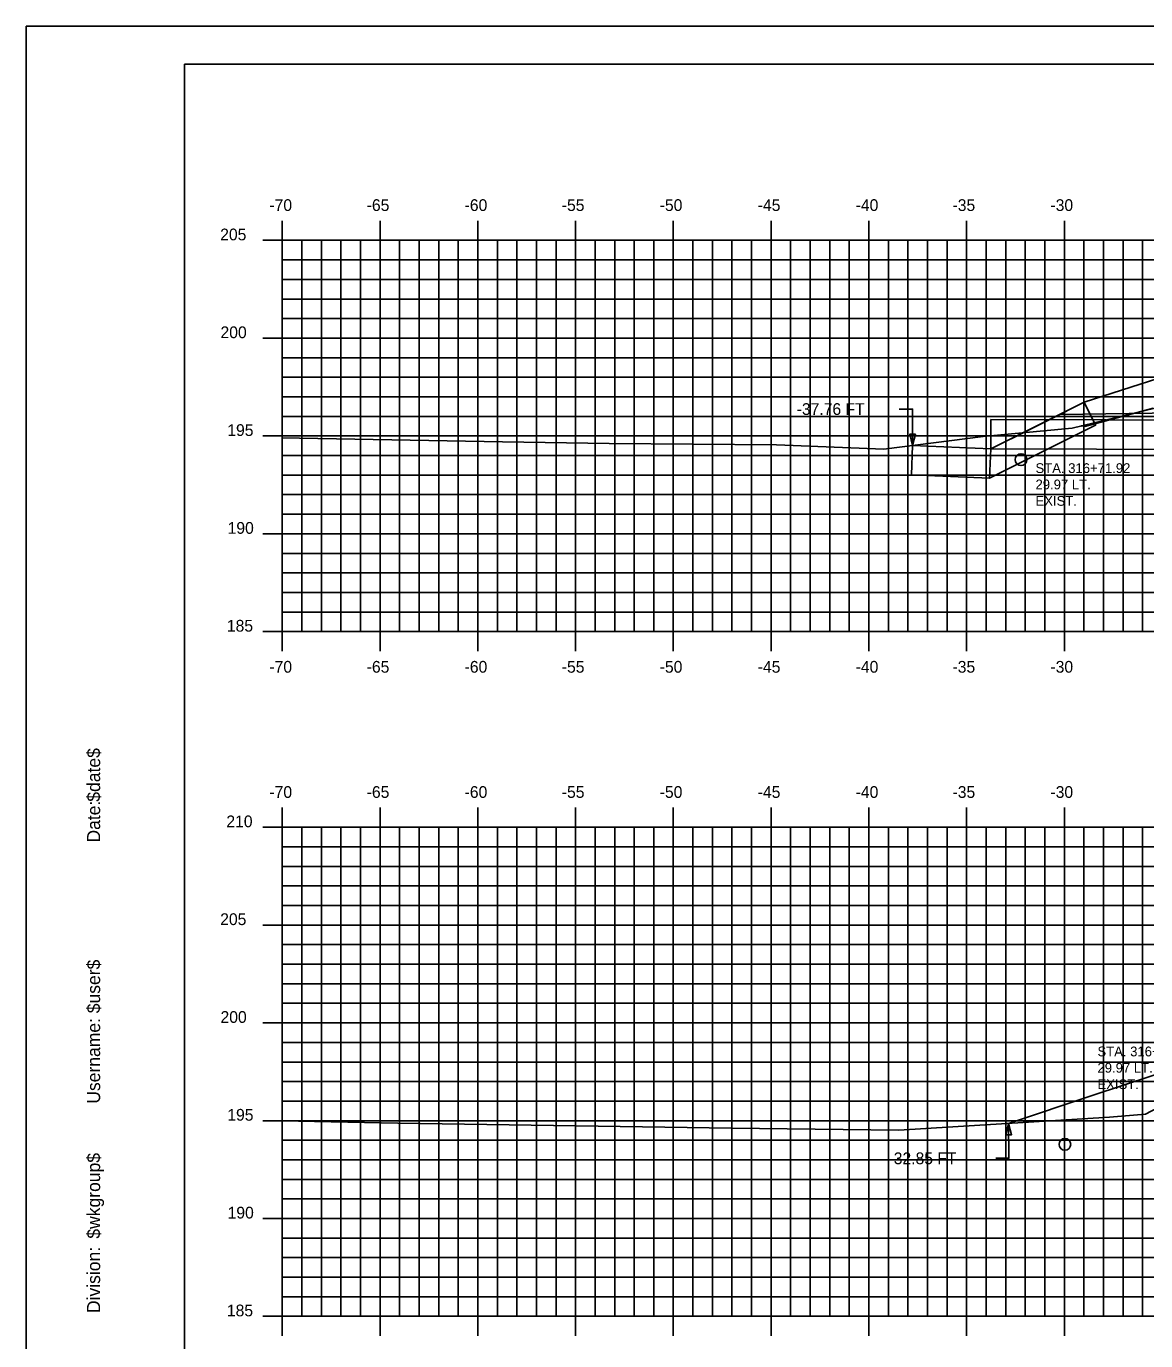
# Model space of a CAD drawing. Extents: x 1138763 to 1138933, y 608981 to 609091.
# Drawn here: x 1138763.1 to 1138820.4, y 609024.1 to 609091.3 of the extents above; entities that cross this region are included whole.
import ezdxf

# ---------------------------------------------------------------- set-up
doc = ezdxf.new("R2010")
doc.units = 0
for name, color, linetype in [('BORDER', 7, 'Continuous'), ('D_Drainage_Culvert', 7, 'Continuous'), ('D_Roadway_SlopeLines', 7, 'Continuous'), ('D_Roadway_SubGrade', 7, 'Continuous'), ('D_Text_Monospaced', 7, 'Continuous'), ('D_Text_Standard', 7, 'Continuous'), ('H_V ANNOTATION', 7, 'Continuous'), ('MAJOR', 7, 'Continuous'), ('MINOR', 7, 'Continuous'), ('PATTERNING', 7, 'Continuous'), ('PLOT BOUNDARY', 7, 'Continuous'), ('S_Drainage_Invert', 7, 'Continuous'), ('S_Roadway_Centerline', 7, 'Continuous')]:
    doc.layers.add(name, color=color, linetype=linetype)

msp = doc.modelspace()

# ---------------------------------------------------------------- linework, layer by layer
for points in [[(1138817.029, 609070.836), (1138817.072, 609070.848), (1138817.11, 609070.853), (1138817.15, 609070.852), (1138817.193, 609070.843), (1138817.227, 609070.831), (1138817.236, 609070.827), (1138817.237, 609070.827), (1138818.443, 609071.146), (1138819.083, 609071.315), (1138819.656, 609071.467), (1138820.738, 609071.753)], [(1138813.338, 609035.196), (1138817.659, 609036.636), (1138820.659, 609037.636), (1138828.191, 609040.147), (1138828.192, 609040.147), (1138835.192, 609040.427), (1138846.192, 609040.647), (1138857.192, 609040.427), (1138870.385, 609039.899), (1138877.65, 609037.478), (1138880.65, 609036.478), (1138886.526, 609034.519)]]:
    msp.add_lwpolyline(points)
at = {"layer": 'BORDER'}
msp.add_lwpolyline([(1138771.192, 608984.335), (1138931.192, 608984.335), (1138931.192, 609089.335), (1138771.192, 609089.335)], close=True, dxfattribs=at)
at = {"layer": 'D_Drainage_Culvert'}
msp.add_lwpolyline([(1138812.433, 609069.671), (1138877.192, 609069.481), (1138877.196, 609070.981), (1138812.438, 609071.171)], close=True, dxfattribs=at)
at = {"layer": 'D_Roadway_SlopeLines'}
for points in [[(1138820.659, 609037.636), (1138817.659, 609036.636)], [(1138817.659, 609036.636), (1138813.338, 609035.196)]]:
    msp.add_lwpolyline(points, dxfattribs=at)
at = {"layer": 'D_Roadway_SubGrade'}
msp.add_line((1138834.369, 609071.704), (1138815.942, 609071.425), dxfattribs=at)
for points in [[(1138823.352, 609074.037), (1138823.352, 609074.037), (1138817.205, 609072.057)], [(1138812.433, 609069.671), (1138814.433, 609070.671), (1138815.416, 609071.162), (1138817.205, 609072.057)]]:
    msp.add_lwpolyline(points, dxfattribs=at)
at = {"layer": 'D_Text_Standard'}
for points in [[(1138808.43, 609069.843), (1138808.426, 609071.71), (1138807.746, 609071.71)], [(1138813.338, 609035.196), (1138813.358, 609033.411), (1138812.678, 609033.411)]]:
    msp.add_lwpolyline(points, dxfattribs=at)
for points in [[(1138808.43, 609069.843), (1138808.283, 609070.425), (1138808.574, 609070.426)], [(1138813.338, 609035.196), (1138813.49, 609034.615), (1138813.199, 609034.612)]]:
    msp.add_lwpolyline(points, close=True, dxfattribs=at)
at = {"layer": 'MAJOR'}
for p, q in [((1138776.192, 609081.337), (1138776.192, 609080.335)), ((1138781.192, 609081.337), (1138781.192, 609080.335)), ((1138786.192, 609081.337), (1138786.192, 609080.335)), ((1138791.192, 609081.337), (1138791.192, 609080.335)), ((1138796.192, 609081.337), (1138796.192, 609080.335)), ((1138801.192, 609081.337), (1138801.192, 609080.335)), ((1138806.192, 609081.337), (1138806.192, 609080.335)), ((1138811.192, 609081.337), (1138811.192, 609080.335)), ((1138816.192, 609081.337), (1138816.192, 609080.335)), ((1138775.19, 609080.335), (1138776.192, 609080.335)), ((1138776.192, 609080.335), (1138916.192, 609080.335)), ((1138776.192, 609060.335), (1138776.192, 609080.335)), ((1138776.192, 609060.335), (1138776.192, 609080.335)), ((1138776.192, 609080.335), (1138916.192, 609080.335)), ((1138781.192, 609060.335), (1138781.192, 609080.335)), ((1138786.192, 609060.335), (1138786.192, 609080.335)), ((1138791.192, 609060.335), (1138791.192, 609080.335)), ((1138796.192, 609060.335), (1138796.192, 609080.335)), ((1138801.192, 609060.335), (1138801.192, 609080.335)), ((1138806.192, 609060.335), (1138806.192, 609080.335)), ((1138811.192, 609060.335), (1138811.192, 609080.335)), ((1138816.192, 609060.335), (1138816.192, 609080.335)), ((1138775.19, 609075.335), (1138776.192, 609075.335)), ((1138776.192, 609075.335), (1138916.192, 609075.335)), ((1138775.19, 609070.335), (1138776.192, 609070.335)), ((1138776.192, 609070.335), (1138916.192, 609070.335)), ((1138775.19, 609065.335), (1138776.192, 609065.335)), ((1138776.192, 609065.335), (1138916.192, 609065.335)), ((1138775.19, 609060.335), (1138776.192, 609060.335)), ((1138776.192, 609060.335), (1138916.192, 609060.335)), ((1138776.192, 609060.335), (1138916.192, 609060.335)), ((1138776.192, 609059.333), (1138776.192, 609060.335)), ((1138781.192, 609059.333), (1138781.192, 609060.335)), ((1138786.192, 609059.333), (1138786.192, 609060.335)), ((1138791.192, 609059.333), (1138791.192, 609060.335)), ((1138796.192, 609059.333), (1138796.192, 609060.335)), ((1138801.192, 609059.333), (1138801.192, 609060.335)), ((1138806.192, 609059.333), (1138806.192, 609060.335)), ((1138811.192, 609059.333), (1138811.192, 609060.335)), ((1138816.192, 609059.333), (1138816.192, 609060.335)), ((1138776.192, 609051.337), (1138776.192, 609050.335)), ((1138781.192, 609051.337), (1138781.192, 609050.335)), ((1138786.192, 609051.337), (1138786.192, 609050.335)), ((1138791.192, 609051.337), (1138791.192, 609050.335)), ((1138796.192, 609051.337), (1138796.192, 609050.335)), ((1138801.192, 609051.337), (1138801.192, 609050.335)), ((1138806.192, 609051.337), (1138806.192, 609050.335)), ((1138811.192, 609051.337), (1138811.192, 609050.335)), ((1138816.192, 609051.337), (1138816.192, 609050.335)), ((1138775.19, 609050.335), (1138776.192, 609050.335)), ((1138776.192, 609050.335), (1138916.192, 609050.335)), ((1138776.192, 609025.335), (1138776.192, 609050.335)), ((1138776.192, 609025.335), (1138776.192, 609050.335)), ((1138776.192, 609050.335), (1138916.192, 609050.335)), ((1138781.192, 609025.335), (1138781.192, 609050.335)), ((1138786.192, 609025.335), (1138786.192, 609050.335)), ((1138791.192, 609025.335), (1138791.192, 609050.335)), ((1138796.192, 609025.335), (1138796.192, 609050.335)), ((1138801.192, 609025.335), (1138801.192, 609050.335)), ((1138806.192, 609025.335), (1138806.192, 609050.335)), ((1138811.192, 609025.335), (1138811.192, 609050.335)), ((1138816.192, 609025.335), (1138816.192, 609050.335)), ((1138775.19, 609045.335), (1138776.192, 609045.335)), ((1138776.192, 609045.335), (1138916.192, 609045.335)), ((1138775.19, 609040.335), (1138776.192, 609040.335)), ((1138776.192, 609040.335), (1138916.192, 609040.335)), ((1138775.19, 609035.335), (1138776.192, 609035.335)), ((1138776.192, 609035.335), (1138916.192, 609035.335)), ((1138775.19, 609030.335), (1138776.192, 609030.335)), ((1138776.192, 609030.335), (1138916.192, 609030.335)), ((1138775.19, 609025.335), (1138776.192, 609025.335)), ((1138776.192, 609025.335), (1138916.192, 609025.335)), ((1138776.192, 609025.335), (1138916.192, 609025.335)), ((1138776.192, 609024.333), (1138776.192, 609025.335)), ((1138781.192, 609024.333), (1138781.192, 609025.335)), ((1138786.192, 609024.333), (1138786.192, 609025.335)), ((1138791.192, 609024.333), (1138791.192, 609025.335)), ((1138796.192, 609024.333), (1138796.192, 609025.335)), ((1138801.192, 609024.333), (1138801.192, 609025.335)), ((1138806.192, 609024.333), (1138806.192, 609025.335)), ((1138811.192, 609024.333), (1138811.192, 609025.335)), ((1138816.192, 609024.333), (1138816.192, 609025.335))]:
    msp.add_line(p, q, dxfattribs=at)
at = {"layer": 'MINOR'}
for p, q in [((1138776.192, 609060.335), (1138776.192, 609080.335)), ((1138777.192, 609060.335), (1138777.192, 609080.335)), ((1138778.192, 609060.335), (1138778.192, 609080.335)), ((1138779.192, 609060.335), (1138779.192, 609080.335)), ((1138780.192, 609060.335), (1138780.192, 609080.335)), ((1138782.192, 609060.335), (1138782.192, 609080.335)), ((1138783.192, 609060.335), (1138783.192, 609080.335)), ((1138784.192, 609060.335), (1138784.192, 609080.335)), ((1138785.192, 609060.335), (1138785.192, 609080.335)), ((1138787.192, 609060.335), (1138787.192, 609080.335)), ((1138788.192, 609060.335), (1138788.192, 609080.335)), ((1138789.192, 609060.335), (1138789.192, 609080.335)), ((1138790.192, 609060.335), (1138790.192, 609080.335)), ((1138792.192, 609060.335), (1138792.192, 609080.335)), ((1138793.192, 609060.335), (1138793.192, 609080.335)), ((1138794.192, 609060.335), (1138794.192, 609080.335)), ((1138795.192, 609060.335), (1138795.192, 609080.335)), ((1138797.192, 609060.335), (1138797.192, 609080.335)), ((1138798.192, 609060.335), (1138798.192, 609080.335)), ((1138799.192, 609060.335), (1138799.192, 609080.335)), ((1138800.192, 609060.335), (1138800.192, 609080.335)), ((1138802.192, 609060.335), (1138802.192, 609080.335)), ((1138803.192, 609060.335), (1138803.192, 609080.335)), ((1138804.192, 609060.335), (1138804.192, 609080.335)), ((1138805.192, 609060.335), (1138805.192, 609080.335)), ((1138807.192, 609060.335), (1138807.192, 609080.335)), ((1138808.192, 609060.335), (1138808.192, 609080.335)), ((1138809.192, 609060.335), (1138809.192, 609080.335)), ((1138810.192, 609060.335), (1138810.192, 609080.335)), ((1138812.192, 609060.335), (1138812.192, 609080.335)), ((1138813.192, 609060.335), (1138813.192, 609080.335)), ((1138814.192, 609060.335), (1138814.192, 609080.335)), ((1138815.192, 609060.335), (1138815.192, 609080.335)), ((1138817.192, 609060.335), (1138817.192, 609080.335)), ((1138818.192, 609060.335), (1138818.192, 609080.335)), ((1138819.192, 609060.335), (1138819.192, 609080.335)), ((1138820.192, 609060.335), (1138820.192, 609080.335)), ((1138776.192, 609079.335), (1138916.192, 609079.335)), ((1138776.192, 609079.335), (1138777.194, 609079.335)), ((1138776.192, 609078.335), (1138916.192, 609078.335)), ((1138776.192, 609078.335), (1138777.194, 609078.335)), ((1138776.192, 609077.335), (1138916.192, 609077.335)), ((1138776.192, 609077.335), (1138777.194, 609077.335)), ((1138776.192, 609076.335), (1138916.192, 609076.335)), ((1138776.192, 609076.335), (1138777.194, 609076.335)), ((1138776.192, 609074.335), (1138916.192, 609074.335)), ((1138776.192, 609074.335), (1138777.194, 609074.335)), ((1138776.192, 609073.335), (1138916.192, 609073.335)), ((1138776.192, 609073.335), (1138777.194, 609073.335)), ((1138776.192, 609072.335), (1138916.192, 609072.335)), ((1138776.192, 609072.335), (1138777.194, 609072.335)), ((1138776.192, 609071.335), (1138916.192, 609071.335)), ((1138776.192, 609071.335), (1138777.194, 609071.335)), ((1138776.192, 609069.335), (1138916.192, 609069.335)), ((1138776.192, 609069.335), (1138777.194, 609069.335)), ((1138776.192, 609068.335), (1138916.192, 609068.335)), ((1138776.192, 609068.335), (1138777.194, 609068.335)), ((1138776.192, 609067.335), (1138916.192, 609067.335)), ((1138776.192, 609067.335), (1138777.194, 609067.335)), ((1138776.192, 609066.335), (1138916.192, 609066.335)), ((1138776.192, 609066.335), (1138777.194, 609066.335)), ((1138776.192, 609064.335), (1138916.192, 609064.335)), ((1138776.192, 609064.335), (1138777.194, 609064.335)), ((1138776.192, 609063.335), (1138916.192, 609063.335)), ((1138776.192, 609063.335), (1138777.194, 609063.335)), ((1138776.192, 609062.335), (1138916.192, 609062.335)), ((1138776.192, 609062.335), (1138777.194, 609062.335)), ((1138776.192, 609061.335), (1138916.192, 609061.335)), ((1138776.192, 609061.335), (1138777.194, 609061.335)), ((1138777.192, 609025.335), (1138777.192, 609050.335)), ((1138778.192, 609025.335), (1138778.192, 609050.335)), ((1138779.192, 609025.335), (1138779.192, 609050.335)), ((1138780.192, 609025.335), (1138780.192, 609050.335)), ((1138782.192, 609025.335), (1138782.192, 609050.335)), ((1138783.192, 609025.335), (1138783.192, 609050.335)), ((1138784.192, 609025.335), (1138784.192, 609050.335)), ((1138785.192, 609025.335), (1138785.192, 609050.335)), ((1138787.192, 609025.335), (1138787.192, 609050.335)), ((1138788.192, 609025.335), (1138788.192, 609050.335)), ((1138789.192, 609025.335), (1138789.192, 609050.335)), ((1138790.192, 609025.335), (1138790.192, 609050.335)), ((1138792.192, 609025.335), (1138792.192, 609050.335)), ((1138793.192, 609025.335), (1138793.192, 609050.335)), ((1138794.192, 609025.335), (1138794.192, 609050.335)), ((1138795.192, 609025.335), (1138795.192, 609050.335)), ((1138797.192, 609025.335), (1138797.192, 609050.335)), ((1138798.192, 609025.335), (1138798.192, 609050.335)), ((1138799.192, 609025.335), (1138799.192, 609050.335)), ((1138800.192, 609025.335), (1138800.192, 609050.335)), ((1138802.192, 609025.335), (1138802.192, 609050.335)), ((1138803.192, 609025.335), (1138803.192, 609050.335)), ((1138804.192, 609025.335), (1138804.192, 609050.335)), ((1138805.192, 609025.335), (1138805.192, 609050.335)), ((1138807.192, 609025.335), (1138807.192, 609050.335)), ((1138808.192, 609025.335), (1138808.192, 609050.335)), ((1138809.192, 609025.335), (1138809.192, 609050.335)), ((1138810.192, 609025.335), (1138810.192, 609050.335)), ((1138812.192, 609025.335), (1138812.192, 609050.335)), ((1138813.192, 609025.335), (1138813.192, 609050.335)), ((1138814.192, 609025.335), (1138814.192, 609050.335)), ((1138815.192, 609025.335), (1138815.192, 609050.335)), ((1138817.192, 609025.335), (1138817.192, 609050.335)), ((1138818.192, 609025.335), (1138818.192, 609050.335)), ((1138819.192, 609025.335), (1138819.192, 609050.335)), ((1138820.192, 609025.335), (1138820.192, 609050.335)), ((1138776.192, 609049.335), (1138916.192, 609049.335)), ((1138776.192, 609049.335), (1138777.194, 609049.335)), ((1138776.192, 609048.335), (1138916.192, 609048.335)), ((1138776.192, 609048.335), (1138777.194, 609048.335)), ((1138776.192, 609047.335), (1138916.192, 609047.335)), ((1138776.192, 609047.335), (1138777.194, 609047.335)), ((1138776.192, 609046.335), (1138916.192, 609046.335)), ((1138776.192, 609046.335), (1138777.194, 609046.335)), ((1138776.192, 609044.335), (1138916.192, 609044.335)), ((1138776.192, 609044.335), (1138777.194, 609044.335)), ((1138776.192, 609043.335), (1138916.192, 609043.335)), ((1138776.192, 609043.335), (1138777.194, 609043.335)), ((1138776.192, 609042.335), (1138916.192, 609042.335)), ((1138776.192, 609042.335), (1138777.194, 609042.335)), ((1138776.192, 609041.335), (1138916.192, 609041.335)), ((1138776.192, 609041.335), (1138777.194, 609041.335)), ((1138776.192, 609039.335), (1138916.192, 609039.335)), ((1138776.192, 609039.335), (1138777.194, 609039.335)), ((1138776.192, 609038.335), (1138916.192, 609038.335)), ((1138776.192, 609038.335), (1138777.194, 609038.335)), ((1138776.192, 609037.335), (1138916.192, 609037.335)), ((1138776.192, 609037.335), (1138777.194, 609037.335)), ((1138776.192, 609036.335), (1138916.192, 609036.335)), ((1138776.192, 609036.335), (1138777.194, 609036.335)), ((1138776.192, 609034.335), (1138916.192, 609034.335)), ((1138776.192, 609034.335), (1138777.194, 609034.335)), ((1138776.192, 609033.335), (1138916.192, 609033.335)), ((1138776.192, 609033.335), (1138777.194, 609033.335)), ((1138776.192, 609032.335), (1138916.192, 609032.335)), ((1138776.192, 609032.335), (1138777.194, 609032.335)), ((1138776.192, 609031.335), (1138916.192, 609031.335)), ((1138776.192, 609031.335), (1138777.194, 609031.335)), ((1138776.192, 609029.335), (1138916.192, 609029.335)), ((1138776.192, 609029.335), (1138777.194, 609029.335)), ((1138776.192, 609028.335), (1138916.192, 609028.335)), ((1138776.192, 609028.335), (1138777.194, 609028.335)), ((1138776.192, 609027.335), (1138916.192, 609027.335)), ((1138776.192, 609027.335), (1138777.194, 609027.335)), ((1138776.192, 609026.335), (1138916.192, 609026.335)), ((1138776.192, 609026.335), (1138777.194, 609026.335))]:
    msp.add_line(p, q, dxfattribs=at)
at = {"layer": 'PATTERNING'}
for points in [[(1138812.369, 609068.172), (1138817.791, 609070.884), (1138817.205, 609072.057), (1138812.433, 609069.671)], [(1138812.433, 609069.671), (1138808.43, 609069.843), (1138808.366, 609068.345), (1138812.369, 609068.172)]]:
    msp.add_lwpolyline(points, close=True, dxfattribs=at)
at = {"layer": 'PLOT BOUNDARY'}
msp.add_lwpolyline([(1138763.099, 608981.276), (1138933.099, 608981.276), (1138933.099, 609091.276), (1138763.099, 609091.276)], close=True, dxfattribs=at)
at = {"layer": 'S_Drainage_Invert'}
for centre in [(1138813.976, 609069.125), (1138816.219, 609034.125)]:
    msp.add_circle(centre, 0.3, dxfattribs=at)
at = {"layer": 'S_Roadway_Centerline'}
for points in [[(1138776.192, 609070.247), (1138777.074, 609070.227), (1138787.458, 609070.03), (1138792.919, 609069.958), (1138801.475, 609069.879), (1138806.958, 609069.657), (1138812.045, 609070.302), (1138816.585, 609070.727), (1138822.444, 609072.146)], [(1138776.192, 609035.323), (1138777.839, 609035.287), (1138782.106, 609035.205), (1138799.163, 609034.953), (1138807.72, 609034.85), (1138818.493, 609035.513), (1138820.336, 609035.676), (1138822.802, 609036.959), (1138826.155, 609038.193), (1138829.472, 609039.241), (1138833.76, 609039.704), (1138836.101, 609040.058), (1138845.533, 609040.114), (1138847.011, 609040.126), (1138856.26, 609039.805), (1138857.396, 609039.779), (1138858.429, 609039.664), (1138864.888, 609039.138), (1138875.538, 609035.078), (1138876.974, 609034.457), (1138879.453, 609034.457), (1138896.104, 609034.7), (1138916.192, 609034.474)]]:
    msp.add_lwpolyline(points, dxfattribs=at)

# ---------------------------------------------------------------- texts
at = {"layer": 'BORDER'}
for s, p in [('$date$', (1138766.877, 609051.64)), ('Date:', (1138766.877, 609049.552)), ('$user$', (1138766.877, 609040.827)), ('Username:', (1138766.877, 609036.203)), ('$wkgroup$', (1138766.877, 609029.305)), ('Division:', (1138766.877, 609025.501))]:
    msp.add_text(s, height=0.6696, rotation=90, dxfattribs=at).set_placement(p)
at = {"layer": 'D_Text_Monospaced'}
for s, height, p in [('STA. 316+71.92', 0.49998, (1138814.716, 609068.441)), ('29.97 LT.', 0.5, (1138814.716, 609067.607)), ('EXIST. ', 0.5, (1138814.716, 609066.767)), ('STA. 316+71.92', 0.49998, (1138817.885, 609038.623)), ('29.97 LT.', 0.5, (1138817.885, 609037.789)), ('EXIST. ', 0.5, (1138817.885, 609036.949))]:
    msp.add_text(s, height=height, dxfattribs=at).set_placement(p)
at = {"layer": 'D_Text_Standard'}
for s, p in [('-37.76 FT', (1138802.501, 609071.41)), ('-32.85 FT', (1138807.198, 609033.111))]:
    msp.add_text(s, height=0.6, dxfattribs=at).set_placement(p)
at = {"layer": 'H_V ANNOTATION'}
for s, p in [('-70', (1138775.534, 609081.835)), ('-65', (1138780.51, 609081.835)), ('-60', (1138785.518, 609081.835)), ('-55', (1138790.488, 609081.835)), ('-50', (1138795.496, 609081.835)), ('-45', (1138800.51, 609081.835)), ('-40', (1138805.518, 609081.835)), ('-35', (1138810.472, 609081.835)), ('-30', (1138815.48, 609081.835)), ('205', (1138773.017, 609080.335)), ('200', (1138773.033, 609075.335)), ('195', (1138773.381, 609070.335)), ('190', (1138773.397, 609065.335)), ('185', (1138773.359, 609060.335)), ('-70', (1138775.534, 609058.235)), ('-65', (1138780.51, 609058.235)), ('-60', (1138785.518, 609058.235)), ('-55', (1138790.488, 609058.235)), ('-50', (1138795.496, 609058.235)), ('-45', (1138800.51, 609058.235)), ('-40', (1138805.518, 609058.235)), ('-35', (1138810.472, 609058.235)), ('-30', (1138815.48, 609058.235)), ('-70', (1138775.534, 609051.835)), ('-65', (1138780.51, 609051.835)), ('-60', (1138785.518, 609051.835)), ('-55', (1138790.488, 609051.835)), ('-50', (1138795.496, 609051.835)), ('-45', (1138800.51, 609051.835)), ('-40', (1138805.518, 609051.835)), ('-35', (1138810.472, 609051.835)), ('-30', (1138815.48, 609051.835)), ('210', (1138773.333, 609050.335)), ('205', (1138773.017, 609045.335)), ('200', (1138773.033, 609040.335)), ('195', (1138773.381, 609035.335)), ('190', (1138773.397, 609030.335)), ('185', (1138773.359, 609025.335))]:
    msp.add_text(s, height=0.6, dxfattribs=at).set_placement(p)
at = {"layer": 'MAJOR'}
for p in [(1138776.188, 609060.335), (1138776.188, 609025.335)]:
    msp.add_text('-', height=0.006, dxfattribs=at).set_placement(p)

doc.saveas('drawing.dxf')
